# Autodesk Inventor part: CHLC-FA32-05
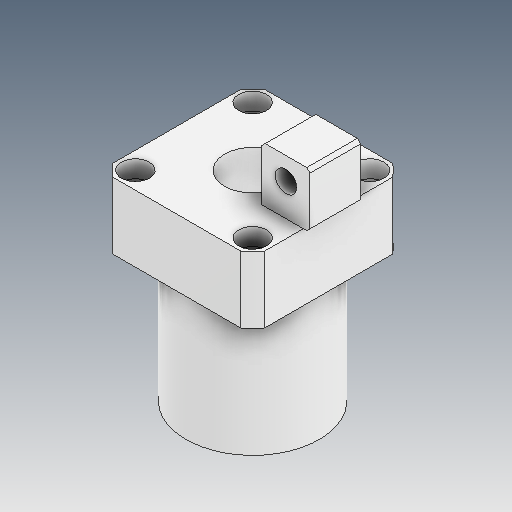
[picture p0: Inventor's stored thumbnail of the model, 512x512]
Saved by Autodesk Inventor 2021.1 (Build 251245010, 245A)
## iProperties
Created: 2021-05
Part Number: CHLC-FA32-05
Material: Ogólny
Document SubType Name: Modeling
Designer: user
Density: 1 g/cm^3
Appearance: Domyślna
Author: user
Revision Number: ÈÎºÎ
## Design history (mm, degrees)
feature "ÊäÈë1"
node "Bryła1"
